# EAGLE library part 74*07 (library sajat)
Hex BUFFER, open collector high-voltage output
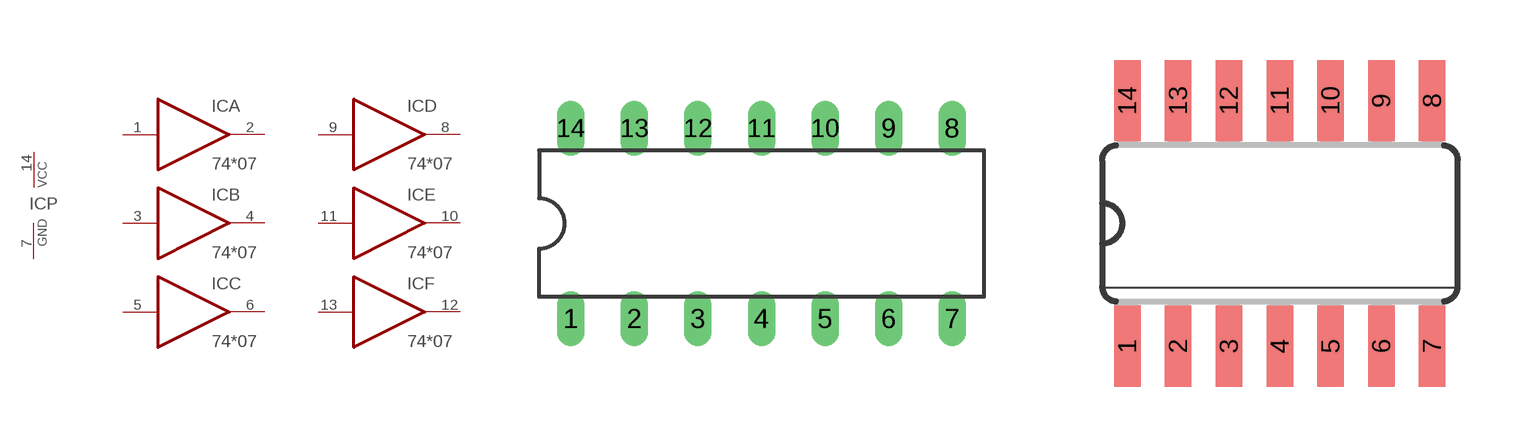
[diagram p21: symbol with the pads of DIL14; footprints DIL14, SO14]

Designator prefix IC; gates A=7407 B=7407 C=7407 D=7407 E=7407 F=7407 P=PWRN-1

## 7407N, 74LS07N  [DIL14]
1  A:I  in
2  A:O  oc
3  B:I  in
4  B:O  oc
5  C:I  in
6  C:O  oc
7  P:GND  pwr
8  D:O  oc
9  D:I  in
10  E:O  oc
11  E:I  in
12  F:O  oc
13  F:I  in
14  P:VCC  pwr

## 7407D, 74LS07D  [SO14]
Pads as for DIL14

## Footprint DIL14 (pad centres in mm)
Dual In Line Package
drill 0.6 pad 1.016 long: 1 -7.62,-3.81; 2 -5.08,-3.81; 3 -2.54,-3.81; 4 0,-3.81; 5 2.54,-3.81; 6 5.08,-3.81; 7 7.62,-3.81; 8 7.62,3.81; 9 5.08,3.81; 10 2.54,3.81; 11 0,3.81; 12 -2.54,3.81; 13 -5.08,3.81; 14 -7.62,3.81

## Footprint SO14 (pad centres in mm)
Small Outline package 150 mil
smd 0.66 x 2.032: 1 -3.81,-3.073; 2 -2.54,-3.073; 3 -1.27,-3.073; 4 0,-3.073; 5 1.27,-3.073; 6 2.54,-3.073; 7 3.81,-3.073; 8 3.81,3.073; 9 2.54,3.073; 10 1.27,3.073; 11 0,3.073; 12 -1.27,3.073; 13 -2.54,3.073; 14 -3.81,3.073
